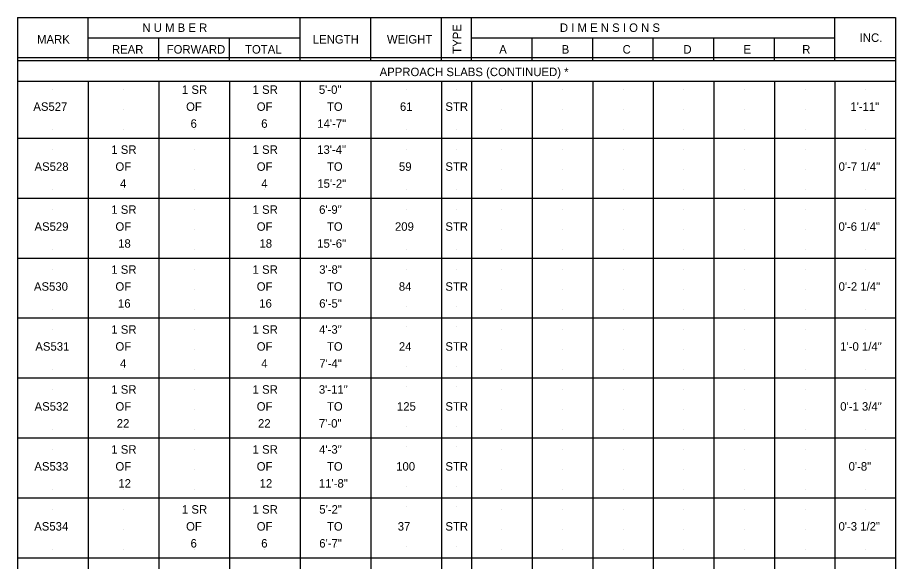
# Model space of a CAD drawing. Extents: x 2.9 to 17.4, y 3.2 to 21.1.
# Drawn here: x 2.87 to 17.37, y 12.07 to 21.05 of the extents above; entities that cross this region are included whole.
import ezdxf

# ---------------------------------------------------------------- set-up
doc = ezdxf.new("R2010")
doc.units = 0
for name, color, linetype in [('BR_P_Gen_Text', 7, 'Continuous'), ('Default', 7, 'Continuous'), ('SC_Scratch1', 7, 'Continuous')]:
    doc.layers.add(name, color=color, linetype=linetype)

msp = doc.modelspace()

# ---------------------------------------------------------------- linework, layer by layer
at = {"layer": 'BR_P_Gen_Text'}
for p, q in [((2.868, 21.052), (17.369, 21.052)), ((4.035, 20.335), (4.035, 21.052)), ((7.535, 20.335), (7.535, 21.052)), ((8.702, 20.335), (8.702, 21.052)), ((9.869, 20.335), (9.869, 21.052)), ((10.369, 20.335), (10.369, 21.052)), ((16.369, 20.335), (16.369, 21.052)), ((17.369, 21.052), (17.369, 3.222)), ((4.035, 20.718), (7.535, 20.718)), ((6.369, 20.335), (6.369, 20.718)), ((10.369, 20.718), (16.369, 20.718)), ((11.369, 20.335), (11.369, 20.718)), ((12.369, 20.335), (12.369, 20.718)), ((13.369, 20.335), (13.369, 20.718)), ((14.369, 20.335), (14.369, 20.718)), ((15.369, 20.335), (15.369, 20.718)), ((17.369, 20.387), (2.868, 20.387)), ((16.024, 20.335), (2.868, 20.335)), ((17.369, 20.335), (2.868, 20.335)), ((2.868, 20.002), (17.369, 20.002)), ((2.868, 20.002), (17.369, 20.002)), ((4.035, 20.002), (4.035, 3.552)), ((5.202, 20.002), (5.202, 3.552)), ((6.369, 20.002), (6.369, 3.552)), ((7.535, 20.002), (7.535, 3.552)), ((8.702, 20.002), (8.702, 3.222)), ((9.869, 20.002), (9.869, 3.222)), ((10.369, 20.002), (10.369, 3.222)), ((11.369, 20.002), (11.369, 3.222)), ((12.369, 20.002), (12.369, 3.222)), ((13.369, 20.002), (13.369, 3.222)), ((14.369, 20.002), (14.369, 3.222)), ((15.369, 20.002), (15.369, 3.222)), ((16.369, 20.002), (16.369, 3.222)), ((2.868, 19.062), (17.369, 19.062)), ((2.868, 18.072), (17.369, 18.072)), ((2.868, 17.082), (17.369, 17.082)), ((2.868, 16.092), (17.369, 16.092)), ((2.868, 15.102), (17.369, 15.102)), ((2.868, 14.112), (17.369, 14.112)), ((2.868, 13.122), (17.369, 13.122)), ((2.868, 12.132), (17.369, 12.132))]:
    msp.add_line(p, q, dxfattribs=at)
at = {"layer": 'Default'}
for p, q in [((2.868, 21.052), (2.868, 3.222)), ((5.202, 20.335), (5.202, 20.718))]:
    msp.add_line(p, q, dxfattribs=at)
at = {"layer": 'SC_Scratch1'}
for p, q in [((3.452, 19.862), (3.452, 19.862)), ((3.452, 19.862), (3.452, 19.862)), ((3.452, 19.862), (3.452, 19.862)), ((4.619, 19.862), (4.619, 19.862)), ((4.619, 19.862), (4.619, 19.862)), ((4.619, 19.862), (4.619, 19.862)), ((5.785, 19.862), (5.785, 19.862)), ((5.785, 19.862), (5.785, 19.862)), ((6.952, 19.862), (6.952, 19.862)), ((8.139, 19.862), (8.139, 19.862)), ((9.285, 19.862), (9.285, 19.862)), ((10.119, 19.862), (10.119, 19.862)), ((10.869, 19.862), (10.869, 19.862)), ((10.869, 19.862), (10.869, 19.862)), ((11.869, 19.862), (11.869, 19.862)), ((11.869, 19.862), (11.869, 19.862)), ((12.869, 19.862), (12.869, 19.862)), ((12.869, 19.862), (12.869, 19.862)), ((13.869, 19.862), (13.869, 19.862)), ((13.869, 19.862), (13.869, 19.862)), ((14.869, 19.862), (14.869, 19.862)), ((14.869, 19.862), (14.869, 19.862)), ((15.891, 19.862), (15.891, 19.862)), ((15.891, 19.862), (15.891, 19.862)), ((16.869, 19.862), (16.869, 19.862)), ((16.869, 19.862), (16.869, 19.862)), ((3.452, 19.532), (3.452, 19.532)), ((3.452, 19.532), (3.452, 19.532)), ((4.619, 19.532), (4.619, 19.532)), ((5.785, 19.532), (5.785, 19.532)), ((5.785, 19.532), (5.785, 19.532)), ((6.952, 19.532), (6.952, 19.532)), ((8.139, 19.532), (8.139, 19.532)), ((9.285, 19.532), (9.285, 19.532)), ((10.119, 19.532), (10.119, 19.532)), ((10.869, 19.532), (10.869, 19.532)), ((10.869, 19.532), (10.869, 19.532)), ((11.869, 19.532), (11.869, 19.532)), ((11.869, 19.532), (11.869, 19.532)), ((12.869, 19.532), (12.869, 19.532)), ((12.869, 19.532), (12.869, 19.532)), ((13.869, 19.532), (13.869, 19.532)), ((13.869, 19.532), (13.869, 19.532)), ((14.869, 19.532), (14.869, 19.532)), ((14.869, 19.532), (14.869, 19.532)), ((15.891, 19.532), (15.891, 19.532)), ((15.891, 19.532), (15.891, 19.532)), ((16.869, 19.532), (16.869, 19.532)), ((16.869, 19.532), (16.869, 19.532)), ((3.452, 19.202), (3.452, 19.202)), ((3.452, 19.202), (3.452, 19.202)), ((4.619, 19.202), (4.619, 19.202)), ((5.785, 19.202), (5.785, 19.202)), ((5.785, 19.202), (5.785, 19.202)), ((6.952, 19.202), (6.952, 19.202)), ((8.139, 19.202), (8.139, 19.202)), ((9.285, 19.202), (9.285, 19.202)), ((10.119, 19.202), (10.119, 19.202)), ((10.869, 19.202), (10.869, 19.202)), ((10.869, 19.202), (10.869, 19.202)), ((11.869, 19.202), (11.869, 19.202)), ((11.869, 19.202), (11.869, 19.202)), ((12.869, 19.202), (12.869, 19.202)), ((12.869, 19.202), (12.869, 19.202)), ((13.869, 19.202), (13.869, 19.202)), ((13.869, 19.202), (13.869, 19.202)), ((14.869, 19.202), (14.869, 19.202)), ((14.869, 19.202), (14.869, 19.202)), ((15.891, 19.202), (15.891, 19.202)), ((15.891, 19.202), (15.891, 19.202)), ((16.869, 19.202), (16.869, 19.202)), ((16.869, 19.202), (16.869, 19.202)), ((3.452, 18.872), (3.452, 18.872)), ((3.452, 18.872), (3.452, 18.872)), ((4.619, 18.872), (4.619, 18.872)), ((5.785, 18.872), (5.785, 18.872)), ((6.952, 18.872), (6.952, 18.872)), ((8.139, 18.872), (8.139, 18.872)), ((9.285, 18.872), (9.285, 18.872)), ((10.119, 18.872), (10.119, 18.872)), ((10.869, 18.872), (10.869, 18.872)), ((10.869, 18.872), (10.869, 18.872)), ((11.869, 18.872), (11.869, 18.872)), ((11.869, 18.872), (11.869, 18.872)), ((12.869, 18.872), (12.869, 18.872)), ((12.869, 18.872), (12.869, 18.872)), ((13.869, 18.872), (13.869, 18.872)), ((13.869, 18.872), (13.869, 18.872)), ((14.869, 18.872), (14.869, 18.872)), ((14.869, 18.872), (14.869, 18.872)), ((15.891, 18.872), (15.891, 18.872)), ((15.891, 18.872), (15.891, 18.872)), ((16.869, 18.872), (16.869, 18.872)), ((16.869, 18.872), (16.869, 18.872)), ((3.452, 18.542), (3.452, 18.542)), ((3.452, 18.542), (3.452, 18.542)), ((4.619, 18.542), (4.619, 18.542)), ((5.785, 18.542), (5.785, 18.542)), ((6.952, 18.542), (6.952, 18.542)), ((8.139, 18.542), (8.139, 18.542)), ((9.285, 18.542), (9.285, 18.542)), ((10.119, 18.542), (10.119, 18.542)), ((10.869, 18.542), (10.869, 18.542)), ((10.869, 18.542), (10.869, 18.542)), ((11.869, 18.542), (11.869, 18.542)), ((11.869, 18.542), (11.869, 18.542)), ((12.869, 18.542), (12.869, 18.542)), ((12.869, 18.542), (12.869, 18.542)), ((13.869, 18.542), (13.869, 18.542)), ((13.869, 18.542), (13.869, 18.542)), ((14.869, 18.542), (14.869, 18.542)), ((14.869, 18.542), (14.869, 18.542)), ((15.891, 18.542), (15.891, 18.542)), ((15.891, 18.542), (15.891, 18.542)), ((16.869, 18.542), (16.869, 18.542)), ((16.869, 18.542), (16.869, 18.542)), ((3.452, 18.212), (3.452, 18.212)), ((3.452, 18.212), (3.452, 18.212)), ((4.619, 18.212), (4.619, 18.212)), ((5.785, 18.212), (5.785, 18.212)), ((6.952, 18.212), (6.952, 18.212)), ((8.139, 18.212), (8.139, 18.212)), ((9.285, 18.212), (9.285, 18.212)), ((10.119, 18.212), (10.119, 18.212)), ((10.869, 18.212), (10.869, 18.212)), ((10.869, 18.212), (10.869, 18.212)), ((11.869, 18.212), (11.869, 18.212)), ((11.869, 18.212), (11.869, 18.212)), ((12.869, 18.212), (12.869, 18.212)), ((12.869, 18.212), (12.869, 18.212)), ((13.869, 18.212), (13.869, 18.212)), ((13.869, 18.212), (13.869, 18.212)), ((14.869, 18.212), (14.869, 18.212)), ((14.869, 18.212), (14.869, 18.212)), ((15.891, 18.212), (15.891, 18.212)), ((15.891, 18.212), (15.891, 18.212)), ((16.869, 18.212), (16.869, 18.212)), ((16.869, 18.212), (16.869, 18.212)), ((3.452, 17.882), (3.452, 17.882)), ((3.452, 17.882), (3.452, 17.882)), ((4.619, 17.882), (4.619, 17.882)), ((5.785, 17.882), (5.785, 17.882)), ((6.952, 17.882), (6.952, 17.882)), ((8.139, 17.882), (8.139, 17.882)), ((9.285, 17.882), (9.285, 17.882)), ((10.119, 17.882), (10.119, 17.882)), ((10.869, 17.882), (10.869, 17.882)), ((10.869, 17.882), (10.869, 17.882)), ((11.869, 17.882), (11.869, 17.882)), ((11.869, 17.882), (11.869, 17.882)), ((12.869, 17.882), (12.869, 17.882)), ((12.869, 17.882), (12.869, 17.882)), ((13.869, 17.882), (13.869, 17.882)), ((13.869, 17.882), (13.869, 17.882)), ((14.869, 17.882), (14.869, 17.882)), ((14.869, 17.882), (14.869, 17.882)), ((15.891, 17.882), (15.891, 17.882)), ((15.891, 17.882), (15.891, 17.882)), ((16.869, 17.882), (16.869, 17.882)), ((16.869, 17.882), (16.869, 17.882)), ((3.452, 17.552), (3.452, 17.552)), ((3.452, 17.552), (3.452, 17.552)), ((4.619, 17.552), (4.619, 17.552)), ((5.785, 17.552), (5.785, 17.552)), ((6.952, 17.552), (6.952, 17.552)), ((8.139, 17.552), (8.139, 17.552)), ((9.285, 17.552), (9.285, 17.552)), ((10.119, 17.552), (10.119, 17.552)), ((10.869, 17.552), (10.869, 17.552)), ((10.869, 17.552), (10.869, 17.552)), ((11.869, 17.552), (11.869, 17.552)), ((11.869, 17.552), (11.869, 17.552)), ((12.869, 17.552), (12.869, 17.552)), ((12.869, 17.552), (12.869, 17.552)), ((13.869, 17.552), (13.869, 17.552)), ((13.869, 17.552), (13.869, 17.552)), ((14.869, 17.552), (14.869, 17.552)), ((14.869, 17.552), (14.869, 17.552)), ((15.891, 17.552), (15.891, 17.552)), ((15.891, 17.552), (15.891, 17.552)), ((16.869, 17.552), (16.869, 17.552)), ((16.869, 17.552), (16.869, 17.552)), ((3.452, 17.222), (3.452, 17.222)), ((3.452, 17.222), (3.452, 17.222)), ((4.619, 17.222), (4.619, 17.222)), ((5.785, 17.222), (5.785, 17.222)), ((6.952, 17.222), (6.952, 17.222)), ((8.139, 17.222), (8.139, 17.222)), ((9.285, 17.222), (9.285, 17.222)), ((10.119, 17.222), (10.119, 17.222)), ((10.869, 17.222), (10.869, 17.222)), ((10.869, 17.222), (10.869, 17.222)), ((11.869, 17.222), (11.869, 17.222)), ((11.869, 17.222), (11.869, 17.222)), ((12.869, 17.222), (12.869, 17.222)), ((12.869, 17.222), (12.869, 17.222)), ((13.869, 17.222), (13.869, 17.222)), ((13.869, 17.222), (13.869, 17.222)), ((14.869, 17.222), (14.869, 17.222)), ((14.869, 17.222), (14.869, 17.222)), ((15.891, 17.222), (15.891, 17.222)), ((15.891, 17.222), (15.891, 17.222)), ((16.869, 17.222), (16.869, 17.222)), ((16.869, 17.222), (16.869, 17.222)), ((3.452, 16.892), (3.452, 16.892)), ((3.452, 16.892), (3.452, 16.892)), ((4.619, 16.892), (4.619, 16.892)), ((5.785, 16.892), (5.785, 16.892)), ((6.952, 16.892), (6.952, 16.892)), ((8.139, 16.892), (8.139, 16.892)), ((9.285, 16.892), (9.285, 16.892)), ((10.119, 16.892), (10.119, 16.892)), ((10.869, 16.892), (10.869, 16.892)), ((10.869, 16.892), (10.869, 16.892)), ((11.869, 16.892), (11.869, 16.892)), ((11.869, 16.892), (11.869, 16.892)), ((12.869, 16.892), (12.869, 16.892)), ((12.869, 16.892), (12.869, 16.892)), ((13.869, 16.892), (13.869, 16.892)), ((13.869, 16.892), (13.869, 16.892)), ((14.869, 16.892), (14.869, 16.892)), ((14.869, 16.892), (14.869, 16.892)), ((15.891, 16.892), (15.891, 16.892)), ((15.891, 16.892), (15.891, 16.892)), ((16.869, 16.892), (16.869, 16.892)), ((16.869, 16.892), (16.869, 16.892)), ((3.452, 16.562), (3.452, 16.562)), ((4.619, 16.562), (4.619, 16.562)), ((5.785, 16.562), (5.785, 16.562)), ((6.952, 16.612), (6.952, 16.612)), ((8.139, 16.562), (8.139, 16.562)), ((9.285, 16.562), (9.285, 16.562)), ((10.119, 16.562), (10.119, 16.562)), ((10.869, 16.562), (10.869, 16.562)), ((11.869, 16.562), (11.869, 16.562)), ((12.869, 16.562), (12.869, 16.562)), ((13.869, 16.562), (13.869, 16.562)), ((14.869, 16.562), (14.869, 16.562)), ((15.891, 16.562), (15.891, 16.562)), ((16.869, 16.562), (16.869, 16.562)), ((6.952, 16.282), (6.952, 16.282)), ((8.139, 16.282), (8.139, 16.282)), ((9.285, 16.282), (9.285, 16.282)), ((10.119, 16.282), (10.119, 16.282)), ((3.452, 16.232), (3.452, 16.232)), ((4.619, 16.232), (4.619, 16.232)), ((5.785, 16.232), (5.785, 16.232)), ((10.869, 16.232), (10.869, 16.232)), ((11.869, 16.232), (11.869, 16.232)), ((12.869, 16.232), (12.869, 16.232)), ((13.869, 16.232), (13.869, 16.232)), ((14.869, 16.232), (14.869, 16.232)), ((15.891, 16.232), (15.891, 16.232)), ((16.869, 16.232), (16.869, 16.232)), ((6.952, 15.952), (6.952, 15.952)), ((8.139, 15.952), (8.139, 15.952)), ((9.285, 15.952), (9.285, 15.952)), ((10.119, 15.952), (10.119, 15.952)), ((3.452, 15.902), (3.452, 15.902)), ((4.619, 15.902), (4.619, 15.902)), ((5.785, 15.902), (5.785, 15.902)), ((10.869, 15.902), (10.869, 15.902)), ((11.869, 15.902), (11.869, 15.902)), ((12.869, 15.902), (12.869, 15.902)), ((13.869, 15.902), (13.869, 15.902)), ((14.869, 15.902), (14.869, 15.902)), ((15.891, 15.902), (15.891, 15.902)), ((16.869, 15.902), (16.869, 15.902)), ((3.452, 15.572), (3.452, 15.572)), ((4.619, 15.572), (4.619, 15.572)), ((5.785, 15.572), (5.785, 15.572)), ((6.952, 15.622), (6.952, 15.622)), ((8.139, 15.622), (8.139, 15.622)), ((9.285, 15.622), (9.285, 15.622)), ((10.119, 15.622), (10.119, 15.622)), ((10.869, 15.572), (10.869, 15.572)), ((11.869, 15.572), (11.869, 15.572)), ((12.869, 15.572), (12.869, 15.572)), ((13.869, 15.572), (13.869, 15.572)), ((14.869, 15.572), (14.869, 15.572)), ((15.891, 15.572), (15.891, 15.572)), ((16.869, 15.572), (16.869, 15.572)), ((3.452, 15.242), (3.452, 15.242)), ((4.619, 15.242), (4.619, 15.242)), ((5.785, 15.242), (5.785, 15.242)), ((6.952, 15.292), (6.952, 15.292)), ((8.139, 15.292), (8.139, 15.292)), ((9.285, 15.292), (9.285, 15.292)), ((10.119, 15.292), (10.119, 15.292)), ((10.869, 15.242), (10.869, 15.242)), ((11.869, 15.242), (11.869, 15.242)), ((12.869, 15.242), (12.869, 15.242)), ((13.869, 15.242), (13.869, 15.242)), ((14.869, 15.242), (14.869, 15.242)), ((15.891, 15.242), (15.891, 15.242)), ((16.869, 15.242), (16.869, 15.242)), ((6.952, 14.962), (6.952, 14.962)), ((8.139, 14.962), (8.139, 14.962)), ((9.285, 14.962), (9.285, 14.962)), ((10.119, 14.962), (10.119, 14.962)), ((3.452, 14.912), (3.452, 14.912)), ((4.619, 14.912), (4.619, 14.912)), ((5.785, 14.912), (5.785, 14.912)), ((10.869, 14.912), (10.869, 14.912)), ((11.869, 14.912), (11.869, 14.912)), ((12.869, 14.912), (12.869, 14.912)), ((13.869, 14.912), (13.869, 14.912)), ((14.869, 14.912), (14.869, 14.912)), ((15.891, 14.912), (15.891, 14.912)), ((16.869, 14.912), (16.869, 14.912)), ((3.452, 14.582), (3.452, 14.582)), ((4.619, 14.582), (4.619, 14.582)), ((5.785, 14.582), (5.785, 14.582)), ((6.952, 14.632), (6.952, 14.632)), ((8.139, 14.632), (8.139, 14.632)), ((9.285, 14.632), (9.285, 14.632)), ((10.119, 14.632), (10.119, 14.632)), ((10.869, 14.582), (10.869, 14.582)), ((11.869, 14.582), (11.869, 14.582)), ((12.869, 14.582), (12.869, 14.582)), ((13.869, 14.582), (13.869, 14.582)), ((14.869, 14.582), (14.869, 14.582)), ((15.891, 14.582), (15.891, 14.582)), ((16.869, 14.582), (16.869, 14.582)), ((3.452, 14.252), (3.452, 14.252)), ((4.619, 14.252), (4.619, 14.252)), ((5.785, 14.252), (5.785, 14.252)), ((6.952, 14.302), (6.952, 14.302)), ((8.139, 14.302), (8.139, 14.302)), ((9.285, 14.302), (9.285, 14.302)), ((10.119, 14.302), (10.119, 14.302)), ((10.869, 14.252), (10.869, 14.252)), ((11.869, 14.252), (11.869, 14.252)), ((12.869, 14.252), (12.869, 14.252)), ((13.869, 14.252), (13.869, 14.252)), ((14.869, 14.252), (14.869, 14.252)), ((15.891, 14.252), (15.891, 14.252)), ((16.869, 14.252), (16.869, 14.252)), ((3.452, 13.922), (3.452, 13.922)), ((4.619, 13.922), (4.619, 13.922)), ((5.785, 13.922), (5.785, 13.922)), ((6.952, 13.972), (6.952, 13.972)), ((8.139, 13.972), (8.139, 13.972)), ((9.285, 13.972), (9.285, 13.972)), ((10.119, 13.972), (10.119, 13.972)), ((10.869, 13.922), (10.869, 13.922)), ((11.869, 13.922), (11.869, 13.922)), ((12.869, 13.922), (12.869, 13.922)), ((13.869, 13.922), (13.869, 13.922)), ((14.869, 13.922), (14.869, 13.922)), ((15.891, 13.922), (15.891, 13.922)), ((16.869, 13.922), (16.869, 13.922)), ((6.952, 13.642), (6.952, 13.642)), ((8.139, 13.642), (8.139, 13.642)), ((9.285, 13.642), (9.285, 13.642)), ((10.119, 13.642), (10.119, 13.642)), ((3.452, 13.592), (3.452, 13.592)), ((4.619, 13.592), (4.619, 13.592)), ((5.785, 13.592), (5.785, 13.592)), ((10.869, 13.592), (10.869, 13.592)), ((11.869, 13.592), (11.869, 13.592)), ((12.869, 13.592), (12.869, 13.592)), ((13.869, 13.592), (13.869, 13.592)), ((14.869, 13.592), (14.869, 13.592)), ((15.891, 13.592), (15.891, 13.592)), ((16.869, 13.592), (16.869, 13.592)), ((3.452, 13.262), (3.452, 13.262)), ((4.619, 13.262), (4.619, 13.262)), ((5.785, 13.262), (5.785, 13.262)), ((6.952, 13.312), (6.952, 13.312)), ((8.139, 13.312), (8.139, 13.312)), ((9.285, 13.312), (9.285, 13.312)), ((10.119, 13.312), (10.119, 13.312)), ((10.869, 13.262), (10.869, 13.262)), ((11.869, 13.262), (11.869, 13.262)), ((12.869, 13.262), (12.869, 13.262)), ((13.869, 13.262), (13.869, 13.262)), ((14.869, 13.262), (14.869, 13.262)), ((15.891, 13.262), (15.891, 13.262)), ((16.869, 13.262), (16.869, 13.262)), ((3.452, 12.932), (3.452, 12.932)), ((4.619, 12.932), (4.619, 12.932)), ((5.785, 12.982), (5.785, 12.982)), ((5.785, 12.932), (5.785, 12.932)), ((6.952, 12.982), (6.952, 12.982)), ((8.139, 12.982), (8.139, 12.982)), ((9.285, 12.982), (9.285, 12.982)), ((10.119, 12.982), (10.119, 12.982)), ((10.869, 12.932), (10.869, 12.932)), ((11.869, 12.932), (11.869, 12.932)), ((12.869, 12.932), (12.869, 12.932)), ((13.869, 12.932), (13.869, 12.932)), ((14.869, 12.932), (14.869, 12.932)), ((15.891, 12.932), (15.891, 12.932)), ((16.869, 12.932), (16.869, 12.932)), ((5.785, 12.652), (5.785, 12.652)), ((6.952, 12.652), (6.952, 12.652)), ((8.139, 12.652), (8.139, 12.652)), ((9.285, 12.652), (9.285, 12.652)), ((10.119, 12.652), (10.119, 12.652)), ((3.452, 12.602), (3.452, 12.602)), ((3.452, 12.602), (3.452, 12.602)), ((4.619, 12.602), (4.619, 12.602)), ((5.785, 12.602), (5.785, 12.602)), ((5.785, 12.602), (5.785, 12.602)), ((6.952, 12.602), (6.952, 12.602)), ((10.869, 12.602), (10.869, 12.602)), ((11.869, 12.602), (11.869, 12.602)), ((12.869, 12.602), (12.869, 12.602)), ((13.869, 12.602), (13.869, 12.602)), ((14.869, 12.602), (14.869, 12.602)), ((15.891, 12.602), (15.891, 12.602)), ((16.869, 12.602), (16.869, 12.602)), ((3.452, 12.272), (3.452, 12.272)), ((3.452, 12.272), (3.452, 12.272)), ((3.452, 12.272), (3.452, 12.272)), ((4.619, 12.272), (4.619, 12.272)), ((5.785, 12.322), (5.785, 12.322)), ((5.785, 12.272), (5.785, 12.272)), ((5.785, 12.272), (5.785, 12.272)), ((6.952, 12.322), (6.952, 12.322)), ((6.952, 12.272), (6.952, 12.272)), ((8.139, 12.322), (8.139, 12.322)), ((9.285, 12.322), (9.285, 12.322)), ((10.119, 12.322), (10.119, 12.322)), ((10.869, 12.272), (10.869, 12.272)), ((10.869, 12.272), (10.869, 12.272)), ((11.869, 12.272), (11.869, 12.272)), ((11.869, 12.272), (11.869, 12.272)), ((12.869, 12.272), (12.869, 12.272)), ((12.869, 12.272), (12.869, 12.272)), ((13.869, 12.272), (13.869, 12.272)), ((14.869, 12.272), (14.869, 12.272)), ((15.891, 12.272), (15.891, 12.272)), ((16.869, 12.272), (16.869, 12.272))]:
    msp.add_line(p, q, dxfattribs=at)

# ---------------------------------------------------------------- texts
at = {"layer": 'BR_P_Gen_Text'}
for s, p in [('1 SR', (5.584, 19.792)), ('1 SR', (6.751, 19.792)), ('5\'-0"', (7.845, 19.792)), ('AS527', (3.129, 19.512)), ('OF', (5.652, 19.512)), ('OF', (6.819, 19.512)), ('TO', (7.979, 19.512)), ('61', (9.184, 19.512)), ('STR', (9.935, 19.512)), ('1\'-11"', (16.624, 19.512)), ('6', (5.726, 19.232)), ('6', (6.893, 19.232)), ('14\'-7"', (7.819, 19.232)), ('1 SR', (4.417, 18.802)), ('1 SR', (6.751, 18.802)), ('13\'-4"', (7.817, 18.802)), ('AS528', (3.149, 18.522)), ('OF', (4.485, 18.522)), ('OF', (6.819, 18.522)), ('TO', (7.979, 18.522)), ('59', (9.168, 18.522)), ('STR', (9.935, 18.522)), ('0\'-7 1/4"', (16.43, 18.522)), ('4', (4.56, 18.242)), ('4', (6.894, 18.242)), ('15\'-2"', (7.82, 18.242)), ('1 SR', (4.417, 17.812)), ('1 SR', (6.751, 17.812)), ('6\'-9"', (7.85, 17.812)), ('AS529', (3.148, 17.532)), ('OF', (4.485, 17.532)), ('OF', (6.819, 17.532)), ('TO', (7.979, 17.532)), ('209', (9.102, 17.532)), ('STR', (9.935, 17.532)), ('0\'-6 1/4"', (16.428, 17.532)), ('18', (4.53, 17.252)), ('18', (6.864, 17.252)), ('15\'-6"', (7.818, 17.252)), ('1 SR', (4.417, 16.822)), ('1 SR', (6.751, 16.822)), ('3\'-8"', (7.851, 16.822)), ('AS530', (3.139, 16.542)), ('OF', (4.485, 16.542)), ('OF', (6.819, 16.542)), ('TO', (7.979, 16.542)), ('84', (9.166, 16.542)), ('STR', (9.935, 16.542)), ('0\'-2 1/4"', (16.43, 16.542)), ('16', (4.527, 16.262)), ('16', (6.86, 16.262)), ('6\'-5"', (7.851, 16.262)), ('1 SR', (4.417, 15.832)), ('1 SR', (6.751, 15.832)), ('4\'-3"', (7.85, 15.832)), ('AS531', (3.162, 15.552)), ('OF', (4.485, 15.552)), ('OF', (6.819, 15.552)), ('TO', (7.979, 15.552)), ('24', (9.167, 15.552)), ('STR', (9.935, 15.552)), ('1\'-0 1/4"', (16.457, 15.552)), ('4', (4.56, 15.272)), ('4', (6.894, 15.272)), ('7\'-4"', (7.852, 15.272)), ('1 SR', (4.417, 14.842)), ('1 SR', (6.751, 14.842)), ('3\'-11"', (7.845, 14.842)), ('AS532', (3.15, 14.562)), ('OF', (4.485, 14.562)), ('OF', (6.819, 14.562)), ('TO', (7.979, 14.562)), ('125', (9.135, 14.562)), ('STR', (9.935, 14.562)), ('0\'-1 3/4"', (16.457, 14.562)), ('22', (4.507, 14.282)), ('22', (6.84, 14.282)), ('7\'-0"', (7.846, 14.282)), ('1 SR', (4.417, 13.852)), ('1 SR', (6.751, 13.852)), ('4\'-3"', (7.85, 13.852)), ('AS533', (3.146, 13.572)), ('OF', (4.485, 13.572)), ('OF', (6.819, 13.572)), ('TO', (7.979, 13.572)), ('100', (9.122, 13.572)), ('STR', (9.935, 13.572)), ('0\'-8"', (16.595, 13.572)), ('12', (4.533, 13.292)), ('12', (6.867, 13.292)), ('11\'-8"', (7.846, 13.292)), ('1 SR', (5.584, 12.862)), ('1 SR', (6.751, 12.862)), ('5\'-2"', (7.853, 12.862)), ('AS534', (3.144, 12.582)), ('OF', (5.652, 12.582)), ('OF', (6.819, 12.582)), ('TO', (7.979, 12.582)), ('37', (9.148, 12.582)), ('STR', (9.935, 12.582)), ('0\'-3 1/2"', (16.428, 12.582)), ('6', (5.726, 12.302)), ('6', (6.893, 12.302)), ('6\'-7"', (7.852, 12.302))]:
    msp.add_text(s, height=0.14, dxfattribs=at).set_placement(p)
at = {"layer": 'Default'}
for s, p in [('N U M B E R', (4.93, 20.815)), ('D I M E N S I O N S', (11.826, 20.815)), ('MARK', (3.19, 20.623)), ('LENGTH', (7.745, 20.623)), ('WEIGHT', (8.97, 20.623)), ('INC.', (16.778, 20.65)), ('REAR', (4.427, 20.457)), ('FORWARD', (5.332, 20.457)), ('TOTAL', (6.626, 20.457)), ('A', (10.824, 20.457)), ('B', (11.856, 20.457)), ('C', (12.862, 20.457)), ('D', (13.866, 20.457)), ('E', (14.858, 20.457)), ('R', (15.829, 20.457)), ('APPROACH SLABS (CONTINUED) *', (8.849, 20.085))]:
    msp.add_text(s, height=0.14, dxfattribs=at).set_placement(p)
msp.add_text('TYPE', height=0.14, rotation=90, dxfattribs=at).set_placement((10.198, 20.454))

doc.saveas('drawing.dxf')
